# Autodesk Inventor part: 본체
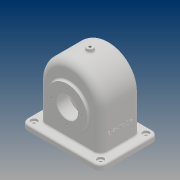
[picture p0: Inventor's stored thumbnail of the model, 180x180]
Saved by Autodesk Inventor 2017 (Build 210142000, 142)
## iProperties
Part Number: 본체
Material: 일반
Document SubType Name: Modeling
Designer: 20
Density: 1 g/cm^3
Appearance: 기본값
Mass: 404.475 g
Surface Area: 1182.21 cm^2
Volume: 404.475 cm^3
Author: 20
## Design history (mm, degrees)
sketch "스케치1"
  geometry: L1 (58, 13)-(58, -65); L2 (-58, 13)-(-58, -65); L3 (58, -65)-(-58, -65); A1 r 58 centre (0, 13) between (58, 13) and (-58, 13); 1 further point
  constraints: 6 end point, 2 point on circle, 2 tangent, 2 vertical, 1 centre point, 1 horizontal, 1 vertical alignment
  dimensions: "d0" = 116 diameter of A1; "d1" = 78 distance of L1.start L1.end; "d2" = 13 distance of point (0, 0) A1.centre
extrude "돌출1" new body sketch "스케치1" stored distance "d3" = 77; taper "d4" = 0 deg
sketch "스케치2"
  geometry: L1 (52, 13)-(52, -65); L2 (-58, -65)-(58, -65) reference; L3 (-52, 13)-(-52, -65); A1 r 52 centre (0, 13) between (52, 13) and (-52, 13); A2 r 58 centre (0, 13) between (58, 13) and (-58, 13) reference; 1 further point
  constraints: 4 end point, 2 point on circle, 2 point on line, 2 tangent, 2 vertical, 1 centre point, 1 concentric
  dimensions: "d5" = 104 diameter of A1
extrude "돌출2" cut sketch "스케치2" stored distance "d6" = 67; taper "d7" = 0 deg
sketch "스케치3"
  geometry: C1 r 38 at (0, 0); 1 further point
  constraints: 1 centre point, 1 coincident
  dimensions: "d8" = 76 diameter of C1
extrude "돌출3" join sketch "스케치3" distance "d9" = 5; taper "d10" = 0 deg
sketch "스케치4"
  geometry: C1 r 28 at (0, 0); 1 further point
  constraints: 1 centre point, 1 coincident
  dimensions: "d11" = 56 diameter of C1
extrude "돌출4" join sketch "스케치4" distance "d12" = 14; taper "d13" = 0 deg
sketch "스케치5"
  geometry: C1 r 38 at (0, 0); 1 further point
  constraints: 1 centre point, 1 coincident
  dimensions: "d14" = 76 diameter of C1
extrude "돌출5" join sketch "스케치5" distance "d15" = 10; taper "d16" = 0 deg
feature "면 기울기1" dims angle "d17" = 40 deg
sketch "스케치7"
  geometry: C1 r 20 at (0, 0); C2 r 38 at (0, 0) reference; 1 further point
  constraints: 1 centre point, 1 concentric
  dimensions: "d18" = 40 diameter of C1
extrude "돌출6" cut sketch "스케치7" stored distance "d19" = 0; taper "d20" = 0 deg
node "작업 평면1"
sketch "스케치8"
  geometry: C1 r 6 at (0, 0); 1 further point
  constraints: 1 centre point, 1 coincident
  dimensions: "d22" = 12 diameter of C1
extrude "돌출7" join sketch "스케치8" stored distance "d23" = 10; taper "d24" = 0 deg
sketch "스케치9"
  geometry: L1 (116, 0)-(116, -77) reference; L2 (116, -77)-(0, -77) reference; L3 (0, 0)-(0, -77) reference; L4 (0, 0)-(116, 0) reference; L5 (133, 16.5)-(-17, 16.5); L6 (-17, 16.5)-(-17, -93.5); L7 (-17, -93.5)-(133, -93.5); L8 (133, -93.5)-(133, 16.5); L9 (133, 16.5)-(-17, -93.5); L10 (-17, 16.5)-(133, -93.5); 1 further point
  constraints: 12 end point, 2 midpoint, 2 parallel, 1 horizontal, 1 perpendicular
  dimensions: "d25" = 150 distance of L7.end L6.end; "d26" = 110 distance of L6.end L5.end
extrude "돌출8" join sketch "스케치9" distance "d27" = 10; taper "d28" = 0 deg
fillet "모깎기1" dims "d29" = 12
sketch "스케치10"
  geometry: L1 (5, 16.5)-(-121, 16.5) reference; L2 (-133, 4.5)-(-133, -81.5) reference; L3 (17, -81.5)-(17, 4.5) reference; L4 (-121, -93.5)-(5, -93.5) reference; 5 further points
  constraints: 2 horizontal alignment, 2 vertical alignment
  dimensions: "d30" = 12 distance from line of L1 point (-121, 4.5); "d31" = 12 distance from line of L2 point (-121, 4.5); "d32" = 12 distance from line of L3 point (5, 4.5); "d33" = 12 distance from line of L4 point (5, -81.5)
hole "구멍1" sketch "스케치10" at (5, 4.5), (-121, 4.5), (-121, -81.5), (5, -81.5) diameter "d34" = 5; stored, may be unused: countersink angle "d38" = 90 deg, drill point angle "d40" = 0 deg; dims "d35" = 6, "d36" = 12, "d37" = 4, "d39" = 10
sketch "스케치11"
  geometry: 2 further points
  constraints: 1 coincident
hole "구멍2" sketch "스케치11" at (0, 0) diameter "d41" = 4.459; stored, may be unused: countersink angle "d45" = 90 deg, drill point angle "d47" = 0 deg; dims "d42" = 10, "d43" = 12, "d44" = 4, "d46" = 12.8
sketch "스케치12" dims "d48" = 58
  geometry: 3 further points
  constraints: 2 horizontal alignment, 1 coincident, 2 other
hole "구멍3" sketch "스케치12" at (29, 0) diameter "d49" = 3.242; stored, may be unused: countersink angle "d53" = 90 deg, drill point angle "d55" = 118 deg; dims "d50" = 8, "d51" = 12, "d52" = 4, "d54" = 10
sketch "스케치13" dims "d59" = 58
  geometry: 3 further points
  constraints: 2 vertical alignment, 1 coincident, 2 other
hole "구멍4" sketch "스케치13" at (0, -29) diameter "d60" = 3.242; stored, may be unused: countersink angle "d64" = 90 deg, drill point angle "d66" = 118 deg; dims "d61" = 8, "d62" = 12, "d63" = 4, "d65" = 10
chamfer "모따기1" distance "d70" = 1; stored, may be unused: second distance "d71" = 2, angle "d72" = 45 deg
fillet "모깎기2" dims "d73" = 13
fillet "모깎기3" dims "d74" = 8
feature "면 기울기2" dims angle "d75" = 5 deg
fillet "모깎기4" dims "d76" = 3
fillet "모깎기5" dims "d77" = 3
sketch "스케치14"
  geometry: L1 (0, -13)-(65, -13) reference; L2 (78, 68.5)-(78, -17.5) reference; 2 further points
  constraints: 1 other
  dimensions: "d78" = 38.5 distance from line of point (38, 25.5) L1; "d79" = 40 distance from line of point (38, 25.5) L2
feature "엠보싱1" sketch "스케치14" dims "d0" = 116, "d1" = 78, "d2" = 13, "d80" = 0.5, "d81" = 0
node "솔리드1"
pattern_circular "원형 패턴1" dims angle "d57" = 360 deg
pattern_circular "원형 패턴2" dims angle "d68" = 360 deg
other parameters: "d21" = 77
